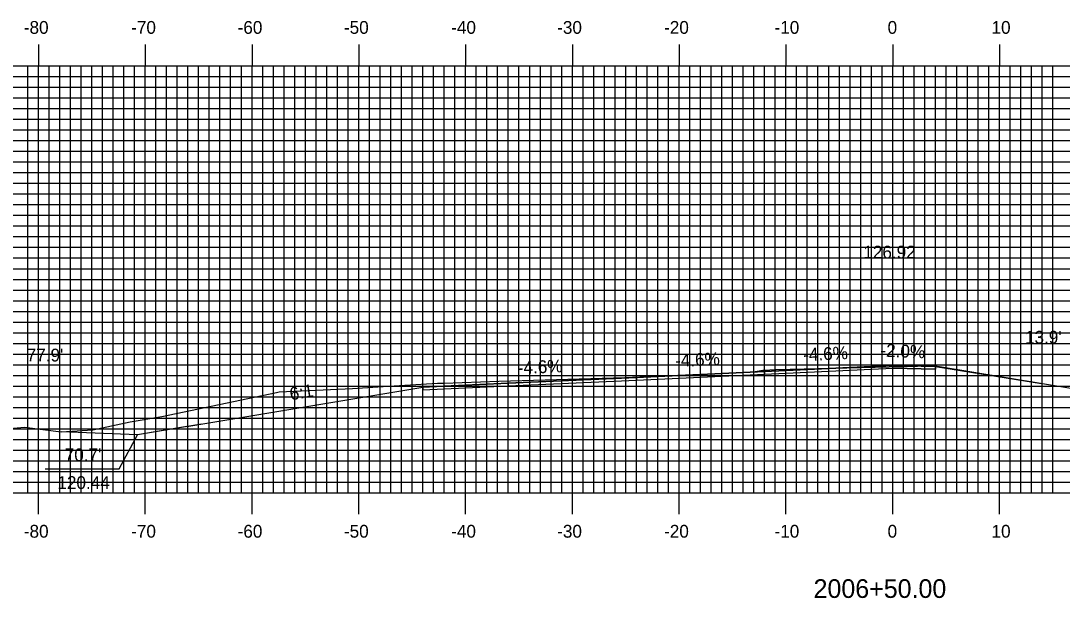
# Model space of a CAD drawing. Extents: x 852320 to 852663, y 366605 to 366825.
# Drawn here: x 852403.8 to 852501.3, y 366673.2 to 366727.3 of the extents above; entities that cross this region are included whole.
import ezdxf

# ---------------------------------------------------------------- set-up
doc = ezdxf.new("R2010")
doc.units = 0
for name, color, linetype in [('ANNOTATION', 7, 'Continuous'), ('D_Roadway_Centerline', 7, 'Continuous'), ('D_Roadway_Centerline_Text', 7, 'Continuous'), ('D_Roadway_Edge_Shoulder', 7, 'Continuous'), ('D_Roadway_Edge_TW', 7, 'Continuous'), ('D_Roadway_SlopeLines', 7, 'Continuous'), ('D_Text_Standard', 7, 'Continuous'), ('H_V ANNOTATION', 7, 'Continuous'), ('M_Roadway_Centerline', 7, 'Continuous'), ('MAJOR', 7, 'Continuous'), ('MINOR', 7, 'Continuous'), ('S_Roadway_Centerline', 7, 'Continuous')]:
    doc.layers.add(name, color=color, linetype=linetype)

msp = doc.modelspace()

# ---------------------------------------------------------------- linework, layer by layer
at = {"layer": 'ANNOTATION'}
for points in [[(852420.759, 366689.499), (852414.759, 366688.499), (852407.617, 366688.77)], [(852406.1, 366685.289), (852413.029, 366685.289), (852414.759, 366688.499)]]:
    msp.add_lwpolyline(points, dxfattribs=at)
at = {"layer": 'D_Roadway_Centerline'}
for p, q in [((852485.478, 366694.976), (852489.478, 366694.896)), ((852485.478, 366694.726), (852489.478, 366694.646))]:
    msp.add_line(p, q, dxfattribs=at)
for points in [[(852419.378, 366689.269), (852441.478, 366692.952), (852444.027, 366693.069), (852449.478, 366693.32), (852461.473, 366693.872), (852461.477, 366693.872), (852473.475, 366694.424), (852473.478, 366694.424), (852485.471, 366694.976), (852485.478, 366694.976), (852489.478, 366694.896)], [(852419.378, 366689.269), (852414.759, 366688.499), (852407.617, 366688.77)]]:
    msp.add_lwpolyline(points, dxfattribs=at)
at = {"layer": 'D_Roadway_Edge_Shoulder'}
for points in [[(852485.478, 366694.976), (852489.478, 366694.896), (852489.478, 366694.646), (852485.478, 366694.726)], [(852449.478, 366693.32), (852441.478, 366692.952), (852441.478, 366692.702), (852449.478, 366693.07)]]:
    msp.add_lwpolyline(points, close=True, dxfattribs=at)
at = {"layer": 'D_Roadway_Edge_TW'}
for points in [[(852485.478, 366694.976), (852473.478, 366694.424), (852473.478, 366694.174), (852485.478, 366694.726)], [(852461.477, 366693.872), (852449.478, 366693.32), (852449.478, 366693.07), (852461.477, 366693.622)], [(852473.478, 366694.424), (852461.477, 366693.872), (852461.477, 366693.622), (852473.478, 366694.174)]]:
    msp.add_lwpolyline(points, close=True, dxfattribs=at)
msp.add_lwpolyline([(852461.477, 366693.622), (852461.477, 366693.872)], dxfattribs=at)
at = {"layer": 'D_Roadway_SlopeLines'}
msp.add_line((852489.478, 366694.896), (852499.418, 366693.313), dxfattribs=at)
at = {"layer": 'MAJOR'}
for p, q in [((852405.478, 366725.059), (852405.478, 366723.055)), ((852415.478, 366725.059), (852415.478, 366723.055)), ((852425.478, 366725.059), (852425.478, 366723.055)), ((852435.478, 366725.059), (852435.478, 366723.055)), ((852445.478, 366725.059), (852445.478, 366723.055)), ((852455.478, 366725.059), (852455.478, 366723.055)), ((852465.478, 366725.059), (852465.478, 366723.055)), ((852475.478, 366725.059), (852475.478, 366723.055)), ((852485.478, 366725.059), (852485.478, 366723.055)), ((852495.478, 366725.059), (852495.478, 366723.055)), ((852345.478, 366723.055), (852625.478, 366723.055)), ((852345.478, 366723.055), (852625.478, 366723.055)), ((852405.478, 366683.055), (852405.478, 366723.055)), ((852415.478, 366683.055), (852415.478, 366723.055)), ((852425.478, 366683.055), (852425.478, 366723.055)), ((852435.478, 366683.055), (852435.478, 366723.055)), ((852445.478, 366683.055), (852445.478, 366723.055)), ((852455.478, 366683.055), (852455.478, 366723.055)), ((852465.478, 366683.055), (852465.478, 366723.055)), ((852475.478, 366683.055), (852475.478, 366723.055)), ((852485.478, 366683.055), (852485.478, 366723.055)), ((852495.478, 366683.055), (852495.478, 366723.055)), ((852345.478, 366718.055), (852625.478, 366718.055)), ((852345.478, 366713.055), (852625.478, 366713.055)), ((852345.478, 366708.055), (852625.478, 366708.055)), ((852345.478, 366703.055), (852625.478, 366703.055)), ((852345.478, 366698.055), (852625.478, 366698.055)), ((852345.478, 366693.055), (852625.478, 366693.055)), ((852345.478, 366688.055), (852625.478, 366688.055)), ((852345.478, 366683.055), (852625.478, 366683.055)), ((852345.478, 366683.055), (852625.478, 366683.055)), ((852405.478, 366681.051), (852405.478, 366683.055)), ((852415.478, 366681.051), (852415.478, 366683.055)), ((852425.478, 366681.051), (852425.478, 366683.055)), ((852435.478, 366681.051), (852435.478, 366683.055)), ((852445.478, 366681.051), (852445.478, 366683.055)), ((852455.478, 366681.051), (852455.478, 366683.055)), ((852465.478, 366681.051), (852465.478, 366683.055)), ((852475.478, 366681.051), (852475.478, 366683.055)), ((852485.478, 366681.051), (852485.478, 366683.055)), ((852495.478, 366681.051), (852495.478, 366683.055))]:
    msp.add_line(p, q, dxfattribs=at)
at = {"layer": 'MINOR'}
for p, q in [((852404.478, 366683.055), (852404.478, 366723.055)), ((852406.478, 366683.055), (852406.478, 366723.055)), ((852407.478, 366683.055), (852407.478, 366723.055)), ((852408.478, 366683.055), (852408.478, 366723.055)), ((852409.478, 366683.055), (852409.478, 366723.055)), ((852410.478, 366683.055), (852410.478, 366723.055)), ((852411.478, 366683.055), (852411.478, 366723.055)), ((852412.478, 366683.055), (852412.478, 366723.055)), ((852413.478, 366683.055), (852413.478, 366723.055)), ((852414.478, 366683.055), (852414.478, 366723.055)), ((852416.478, 366683.055), (852416.478, 366723.055)), ((852417.478, 366683.055), (852417.478, 366723.055)), ((852418.478, 366683.055), (852418.478, 366723.055)), ((852419.478, 366683.055), (852419.478, 366723.055)), ((852420.478, 366683.055), (852420.478, 366723.055)), ((852421.478, 366683.055), (852421.478, 366723.055)), ((852422.478, 366683.055), (852422.478, 366723.055)), ((852423.478, 366683.055), (852423.478, 366723.055)), ((852424.478, 366683.055), (852424.478, 366723.055)), ((852426.478, 366683.055), (852426.478, 366723.055)), ((852427.478, 366683.055), (852427.478, 366723.055)), ((852428.478, 366683.055), (852428.478, 366723.055)), ((852429.478, 366683.055), (852429.478, 366723.055)), ((852430.478, 366683.055), (852430.478, 366723.055)), ((852431.478, 366683.055), (852431.478, 366723.055)), ((852432.478, 366683.055), (852432.478, 366723.055)), ((852433.478, 366683.055), (852433.478, 366723.055)), ((852434.478, 366683.055), (852434.478, 366723.055)), ((852436.478, 366683.055), (852436.478, 366723.055)), ((852437.478, 366683.055), (852437.478, 366723.055)), ((852438.478, 366683.055), (852438.478, 366723.055)), ((852439.478, 366683.055), (852439.478, 366723.055)), ((852440.478, 366683.055), (852440.478, 366723.055)), ((852441.478, 366683.055), (852441.478, 366723.055)), ((852442.478, 366683.055), (852442.478, 366723.055)), ((852443.478, 366683.055), (852443.478, 366723.055)), ((852444.478, 366683.055), (852444.478, 366723.055)), ((852446.478, 366683.055), (852446.478, 366723.055)), ((852447.478, 366683.055), (852447.478, 366723.055)), ((852448.478, 366683.055), (852448.478, 366723.055)), ((852449.478, 366683.055), (852449.478, 366723.055)), ((852450.478, 366683.055), (852450.478, 366723.055)), ((852451.478, 366683.055), (852451.478, 366723.055)), ((852452.478, 366683.055), (852452.478, 366723.055)), ((852453.478, 366683.055), (852453.478, 366723.055)), ((852454.478, 366683.055), (852454.478, 366723.055)), ((852456.478, 366683.055), (852456.478, 366723.055)), ((852457.478, 366683.055), (852457.478, 366723.055)), ((852458.478, 366683.055), (852458.478, 366723.055)), ((852459.478, 366683.055), (852459.478, 366723.055)), ((852460.478, 366683.055), (852460.478, 366723.055)), ((852461.478, 366683.055), (852461.478, 366723.055)), ((852462.478, 366683.055), (852462.478, 366723.055)), ((852463.478, 366683.055), (852463.478, 366723.055)), ((852464.478, 366683.055), (852464.478, 366723.055)), ((852466.478, 366683.055), (852466.478, 366723.055)), ((852467.478, 366683.055), (852467.478, 366723.055)), ((852468.478, 366683.055), (852468.478, 366723.055)), ((852469.478, 366683.055), (852469.478, 366723.055)), ((852470.478, 366683.055), (852470.478, 366723.055)), ((852471.478, 366683.055), (852471.478, 366723.055)), ((852472.478, 366683.055), (852472.478, 366723.055)), ((852473.478, 366683.055), (852473.478, 366723.055)), ((852474.478, 366683.055), (852474.478, 366723.055)), ((852476.478, 366683.055), (852476.478, 366723.055)), ((852477.478, 366683.055), (852477.478, 366723.055)), ((852478.478, 366683.055), (852478.478, 366723.055)), ((852479.478, 366683.055), (852479.478, 366723.055)), ((852480.478, 366683.055), (852480.478, 366723.055)), ((852481.478, 366683.055), (852481.478, 366723.055)), ((852482.478, 366683.055), (852482.478, 366723.055)), ((852483.478, 366683.055), (852483.478, 366723.055)), ((852484.478, 366683.055), (852484.478, 366723.055)), ((852486.478, 366683.055), (852486.478, 366723.055)), ((852487.478, 366683.055), (852487.478, 366723.055)), ((852488.478, 366683.055), (852488.478, 366723.055)), ((852489.478, 366683.055), (852489.478, 366723.055)), ((852490.478, 366683.055), (852490.478, 366723.055)), ((852491.478, 366683.055), (852491.478, 366723.055)), ((852492.478, 366683.055), (852492.478, 366723.055)), ((852493.478, 366683.055), (852493.478, 366723.055)), ((852494.478, 366683.055), (852494.478, 366723.055)), ((852496.478, 366683.055), (852496.478, 366723.055)), ((852497.478, 366683.055), (852497.478, 366723.055)), ((852498.478, 366683.055), (852498.478, 366723.055)), ((852499.478, 366683.055), (852499.478, 366723.055)), ((852500.478, 366683.055), (852500.478, 366723.055)), ((852345.478, 366722.055), (852625.478, 366722.055)), ((852345.478, 366721.055), (852625.478, 366721.055)), ((852345.478, 366720.055), (852625.478, 366720.055)), ((852345.478, 366719.055), (852625.478, 366719.055)), ((852345.478, 366717.055), (852625.478, 366717.055)), ((852345.478, 366716.055), (852625.478, 366716.055)), ((852345.478, 366715.055), (852625.478, 366715.055)), ((852345.478, 366714.055), (852625.478, 366714.055)), ((852345.478, 366712.055), (852625.478, 366712.055)), ((852345.478, 366711.055), (852625.478, 366711.055)), ((852345.478, 366710.055), (852625.478, 366710.055)), ((852345.478, 366709.055), (852625.478, 366709.055)), ((852345.478, 366707.055), (852625.478, 366707.055)), ((852345.478, 366706.055), (852625.478, 366706.055)), ((852345.478, 366705.055), (852625.478, 366705.055)), ((852345.478, 366704.055), (852625.478, 366704.055)), ((852345.478, 366702.055), (852625.478, 366702.055)), ((852345.478, 366701.055), (852625.478, 366701.055)), ((852345.478, 366700.055), (852625.478, 366700.055)), ((852345.478, 366699.055), (852625.478, 366699.055)), ((852345.478, 366697.055), (852625.478, 366697.055)), ((852345.478, 366696.055), (852625.478, 366696.055)), ((852345.478, 366695.055), (852625.478, 366695.055)), ((852345.478, 366694.055), (852625.478, 366694.055)), ((852345.478, 366692.055), (852625.478, 366692.055)), ((852345.478, 366691.055), (852625.478, 366691.055)), ((852345.478, 366690.055), (852625.478, 366690.055)), ((852345.478, 366689.055), (852625.478, 366689.055)), ((852345.478, 366687.055), (852625.478, 366687.055)), ((852345.478, 366686.055), (852625.478, 366686.055)), ((852345.478, 366685.055), (852625.478, 366685.055)), ((852345.478, 366684.055), (852625.478, 366684.055))]:
    msp.add_line(p, q, dxfattribs=at)
at = {"layer": 'S_Roadway_Centerline'}
msp.add_lwpolyline([(852402.8, 366689.084), (852404.163, 366689.209), (852407.617, 366688.77), (852410.558, 366688.964), (852414.08, 366689.719), (852417.047, 366690.207), (852427.781, 366692.466), (852428.028, 366692.508), (852434.894, 366692.844), (852437.26, 366692.972), (852442.853, 366693.323), (852443.451, 366693.318), (852448.595, 366693.503), (852452.919, 366693.635), (852460.378, 366693.857), (852471.73, 366694.355), (852472.604, 366694.429), (852473.298, 366694.558), (852473.391, 366694.556), (852474.531, 366694.603), (852489.133, 366694.951), (852489.423, 366694.954), (852489.434, 366694.956), (852489.868, 366694.905), (852508.969, 366691.721)], dxfattribs=at)

# ---------------------------------------------------------------- texts
at = {"layer": 'ANNOTATION'}
for s, rotation, p in [('-4.6%', 2.63384, (852477.116, 366695.394)), ('-2.0%', 357.70938, (852484.301, 366695.825)), ('-4.6%', 2.63363, (852465.118, 366694.842)), ('-4.6%', 2.6338, (852450.392, 366694.164)), ('6:1', 9.46164, (852429.103, 366691.718)), ("70.7' ", 360, (852407.941, 366686.015)), ('120.44', 360, (852407.251, 366683.415))]:
    msp.add_text(s, height=1.2, rotation=rotation, dxfattribs=at).set_placement(p)
at = {"layer": 'D_Roadway_Centerline_Text'}
msp.add_text('126.92', height=1.2, dxfattribs=at).set_placement((852482.722, 366705.006))
at = {"layer": 'D_Text_Standard'}
for s, p in [("13.9'", (852497.861, 366697.031)), ("77.9'", (852404.376, 366695.359))]:
    msp.add_text(s, height=1.2, dxfattribs=at).set_placement(p)
at = {"layer": 'H_V ANNOTATION'}
for s, height, p in [('-80', 1.2, (852404.108, 366726.055)), ('-70', 1.2, (852414.161, 366726.055)), ('-60', 1.2, (852424.129, 366726.055)), ('-50', 1.2, (852434.086, 366726.055)), ('-40', 1.2, (852444.129, 366726.055)), ('-30', 1.2, (852454.054, 366726.055)), ('-20', 1.2, (852464.065, 366726.055)), ('-10', 1.2, (852474.407, 366726.055)), ('0', 1.2, (852484.996, 366726.055)), ('10', 1.2, (852494.728, 366726.055)), ('-80', 1.2, (852404.108, 366678.855)), ('-70', 1.2, (852414.161, 366678.855)), ('-60', 1.2, (852424.129, 366678.855)), ('-50', 1.2, (852434.086, 366678.855)), ('-40', 1.2, (852444.129, 366678.855)), ('-30', 1.2, (852454.054, 366678.855)), ('-20', 1.2, (852464.065, 366678.855)), ('-10', 1.2, (852474.407, 366678.855)), ('0', 1.2, (852484.996, 366678.855)), ('10', 1.2, (852494.728, 366678.855)), ('2006+50.00', 1.75, (852478.064, 366673.211))]:
    msp.add_text(s, height=height, dxfattribs=at).set_placement(p)
at = {"layer": 'M_Roadway_Centerline'}
for s, p in [('C', (852473.293, 366694.558)), ('L', (852473.298, 366694.551)), ('C', (852442.847, 366693.323)), ('L', (852442.853, 366693.315))]:
    msp.add_text(s, height=0.0146, dxfattribs=at).set_placement(p)

doc.saveas('drawing.dxf')
